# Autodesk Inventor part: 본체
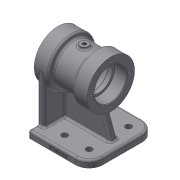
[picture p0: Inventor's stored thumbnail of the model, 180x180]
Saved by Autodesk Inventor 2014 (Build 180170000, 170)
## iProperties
Created: 2020-06
Part Number: 본체
Material: Generic
Document SubType Name: Modeling
Designer: kh
Density: 1 g/cm^3
Appearance: Default
Mass: 268.659 g
Surface Area: 641.338 cm^2
Volume: 268.659 cm^3
Author: kh
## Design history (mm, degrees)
sketch "Sketch1"
  geometry: L1 (-45, -49)-(45, -49); L2 (45, -49)-(45, 49); L3 (45, 49)-(-45, 49); L4 (-45, 49)-(-45, -49); L5 (-45, -49)-(45, 49); L6 (45, -49)-(-45, 49); 1 further point
  constraints: 12 end point, 2 midpoint, 2 parallel, 1 horizontal, 1 perpendicular
  dimensions: "d0" = 98 distance between parallel lines of L1 L3; "d1" = 90 distance between parallel lines of L2 L4
extrude "Extrusion1" new body sketch "Sketch1" distance "d2" = 10; taper "d3" = 0 deg
sketch "Sketch2"
  geometry: L1 (0, 98)-(0, 0) reference; L2 (0, 98)-(10, 98) reference; L3 (80, 84)-(80, 14); L4 (80, 84)-(7, 84); L5 (7, 84)-(7, 14); L6 (7, 14)-(80, 14); 3 further points
  constraints: 8 end point, 3 perpendicular, 2 midpoint, 1 horizontal alignment, 1 parallel
  dimensions: "d4" = 80 distance from line of L3 point (0, 49); "d5" = 70 distance of L3.end L3.start
extrude "Extrusion2" join sketch "Sketch2" distance "d6" = 10; taper "d7" = 0 deg
sketch "Sketch3"
  geometry: L1 (-3.882, 90)-(-33, 10); L2 (-45, 0)-(45, 0) reference; L3 (35, 10)-(45, 10) reference; L4 (45, 10)-(-45, 10) reference; L5 (-45, 10)-(45, 10) reference; L6 (45, 10)-(35, 10) reference; L7 (-3.882, 90)-(40, 90); L8 (40, 90)-(40, 10); L9 (-33, 10)-(40, 10); 1 further point
  constraints: 8 end point, 1 collinear, 1 midpoint, 1 parallel, 1 point on line
  dimensions: "d8" = 12 distance of L1.end L4.end; "d9" = 70 deg angle of L4 L1; "d10" = 80 vertical distance of L1.start L1.end
extrude "Extrusion3" join sketch "Sketch3" stored distance "d11" = 10; taper "d12" = 0 deg
sketch "Sketch4"
  geometry: L1 (50, 115)-(28, 115); L2 (28, 115)-(28, 109); L3 (28, 109)-(-6, 109); L4 (-6, 109)-(-6, 115); L5 (-6, 115)-(-28, 115); L6 (-45, 0)-(45, 0) reference; L7 (45, 0)-(45, 10) reference; L8 (-45, 10)-(45, 10) reference; L9 (-45, 0)-(-45, 10) reference; L10 (50, 80)-(-28, 80); L11 (50, 115)-(50, 80); L12 (-28, 115)-(-28, 80); 4 further points
  constraints: 16 end point, 3 parallel, 3 perpendicular, 2 midpoint, 1 collinear, 1 horizontal, 1 point on line, 1 vertical alignment
  dimensions: "d13" = 78 distance of L5.end L1.start; "d14" = 22 distance of L1.end L1.start; "d15" = 22 distance of L5.end L4.end; "d16" = 5 distance from line of L7 L1.start; "d19" = 80 distance between parallel lines of L6 L10; "d20" = 70 diameter of L1 L10; "d21" = 70 diameter of L5 L10; "d22" = 58 diameter of L3 L10
revolve "Revolution1" sketch "Sketch4" stored, may be unused: angle "d23" = 90 deg
sketch "Sketch5"
  geometry: L1 (56, 80)-(-56, 80); L2 (-45, 0)-(45, 0) reference; L3 (50, 103.5)-(32, 103.5); L4 (32, 103.5)-(32, 100); L5 (32, 100)-(26, 100); L6 (26, 100)-(26, 103); L7 (26, 103)-(-4, 103); L8 (-4, 103)-(-4, 100); L9 (-4, 100)-(-10, 100); L10 (-10, 100)-(-10, 103.5); L11 (-10, 103.5)-(-28, 103.5); L12 (28, 51.434)-(-6, 51.434) reference; L13 (28, 51.434)-(28, 51.434) reference; L14 (-6, 51.434)-(28, 51.434) reference; L15 (-6, 51.434)-(-6, 51.434) reference; L16 (50, 45)-(50, 115) reference; L17 (35, 45.359)-(28, 45.359) reference; L18 (35, 80)-(35, 45.359) reference; L19 (45, 80)-(35, 80) reference; L20 (45, 80)-(45, 80) reference; L21 (45, 80)-(35, 80) reference; L22 (35, 45.359)-(35, 80) reference; L23 (28, 45.359)-(35, 45.359) reference; L24 (28, 45.359)-(28, 45.359) reference; L25 (-6, 45.359)-(-20.13, 45.359) reference; L26 (-6, 45.359)-(-6, 45.359) reference; L27 (-20.13, 45.359)-(-6, 45.359) reference; L28 (-20.13, 45.359)-(-20.13, 45.359) reference; L29 (-28, 45)-(-28, 115) reference; L30 (50, 103.5)-(50, 80); L31 (-28, 103.5)-(-28, 80); L32 (50, 80)-(-28, 80); 2 further points
  constraints: 26 end point, 5 perpendicular, 4 parallel, 3 midpoint, 2 point on line, 1 collinear, 1 horizontal, 1 vertical alignment
  dimensions: "d24" = 80 distance between parallel lines of L2 L1; "d25" = 47 diameter of L3 L1; "d26" = 47 diameter of L11 L1; "d27" = 46 diameter of L7 L1; "d28" = 40 diameter of L5 L1; "d29" = 40 diameter of L9 L1; "d30" = 18 distance of L3.start L3.end; "d31" = 18 distance of L10.end L11.end; "d32" = 30 distance of L6.end L7.end; "d33" = 6 distance of L4.end L5.end
revolve "Revolution2" sketch "Sketch5" stored, may be unused: angle "d34" = 90 deg
sketch "Sketch6"
  geometry: C1 r 23.5 at (0, 0) reference; 2 further points
  constraints: 1 horizontal alignment
  dimensions: "d35" = 28.5 distance of C1.centre point (28.5, 0)
hole "Hole1" sketch "Sketch6" at (28.5, 0) diameter "d36" = 3.242; stored, may be unused: countersink angle "d40" = 90 deg, drill point angle "d42" = 118 deg; dims "d37" = 10, "d38" = 4, "d39" = 2, "d41" = 12
pattern_circular "Circular Pattern1" dims angle "d44" = 360 deg
sketch "Sketch7"
  geometry: C1 r 23.5 at (0, 0) reference; 2 further points
  constraints: 1 horizontal alignment
  dimensions: "d46" = 28.5 distance of C1.centre point (-28.5, 0)
hole "Hole2" sketch "Sketch7" at (-28.5, 0) diameter "d47" = 3.242; stored, may be unused: countersink angle "d51" = 90 deg, drill point angle "d53" = 118 deg; dims "d48" = 10, "d49" = 4, "d50" = 2, "d52" = 12
pattern_circular "Circular Pattern2" dims angle "d55" = 360 deg
workplane "Work Plane1"
sketch "Sketch8"
  geometry: L1 (17, 5)-(-17, 5) reference; L2 (17, -5)-(17, 5) reference; L3 (-17, -5)-(17, -5) reference; L4 (-17, -5)-(-17, 5) reference; C1 r 6 at (0, 0); 2 further points
  constraints: 1 centre point, 1 midpoint, 1 vertical alignment
  dimensions: "d57" = 12 diameter of C1
extrude "Extrusion4" join sketch "Sketch8" stored distance "d58" = 6; taper "d59" = 0 deg
hole "Hole3" diameter "d62" = 5.188; stored, may be unused: countersink angle "d66" = 90 deg, drill point angle "d68" = 0 deg; dims "d60" = 10, "d61" = 10, "d63" = 10, "d64" = 4, "d65" = 2, "d67" = 12
sketch "Sketch9"
  geometry: L1 (-45, -35)-(-45, -49) reference; L2 (-45, 49)-(-45, 35) reference; L3 (-45, -49)-(45, -49) reference; L4 (45, 49)-(-45, 49) reference; 5 further points
  dimensions: "d69" = 70 distance from line of point (25, 29) L2; "d70" = 70 distance from line of point (25, -29) L1; "d71" = 36 distance of point (25, 29) point (-11, 29); "d72" = 36 distance of point (25, -29) point (-11, -29); "d73" = 58 distance of point (25, -29) point (25, 29); "d107" = 20 distance from line of L4 point (25, 29); "d108" = 20 distance from line of L4 point (-11, 29); "d109" = 20 distance from line of L3 point (-11, -29)
hole "Hole4" sketch "Sketch9" at (25, 29), (25, -29), (-11, -29), (-11, 29) diameter "d74" = 9; stored, may be unused: countersink angle "d78" = 90 deg, drill point angle "d80" = 0 deg; dims "d75" = 10, "d76" = 4, "d77" = 2, "d79" = 12
sketch "Sketch10"
  geometry: L1 (0, 0)-(90, 0) reference; L2 (0, 0)-(0, 10) reference; 2 further points
  constraints: 1 other
  dimensions: "d81" = 45 distance from line of point (45, 4) L2; "d82" = 4 distance from line of L1 point (45, 4)
emboss "Emboss1" sketch "Sketch10" dims "d0" = 98, "d1" = 90, "d83" = 0.5, "d84" = 0
fillet "Fillet1" dims "d85" = 0.3
fillet "Fillet2" dims "d86" = 3
fillet "Fillet3" dims "d87" = 3
fillet "Fillet4" dims "d88" = 3
fillet "Fillet6" dims "d90" = 3
fillet "Fillet7" dims "d91" = 3
fillet "Fillet8" dims "d92" = 3
chamfer "Chamfer1" distance "d93" = 1; stored, may be unused: second distance "d94" = 2, angle "d95" = 45 deg
hole "Hole5" diameter "d98" = 5.188; stored, may be unused: countersink angle "d102" = 90 deg, drill point angle "d104" = 0 deg; dims "d96" = 10, "d97" = 10, "d99" = 10, "d100" = 4, "d101" = 2, "d103" = 12
fillet "Fillet10" dims "d106" = 3
fillet "Fillet11" dims "d110" = 20
fillet "Fillet12" dims "d111" = 3
fillet "Fillet13" dims "d112" = 3
body "Solid1"
node "Projected Loop1"
node "Projected Loop2"
node "Projected Loop3"
node "Projected Loop4"
node "Projected Loop5"
node "Projected Loop6"
